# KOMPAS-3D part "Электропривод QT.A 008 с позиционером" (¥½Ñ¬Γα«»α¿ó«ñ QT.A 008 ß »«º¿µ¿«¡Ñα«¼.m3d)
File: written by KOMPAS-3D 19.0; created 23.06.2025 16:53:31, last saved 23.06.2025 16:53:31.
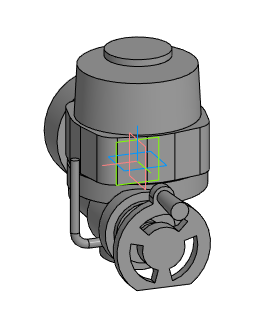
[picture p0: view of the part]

Document properties: Автор: Евгений; Полное имя файла: E:\Dendor Работа Сачек\3D для проектировщиков\3.5 Тип QT.А Электропривод\stp_Электропривод QT.A с позиционером\Электропривод QT.A 008 с позиционером.m3d

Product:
- Part/product: Электропривод QT.A 008 с позиционером

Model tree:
1. Операция без истории:1  (labels: Электропривод QT.A 008 с позиционером)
